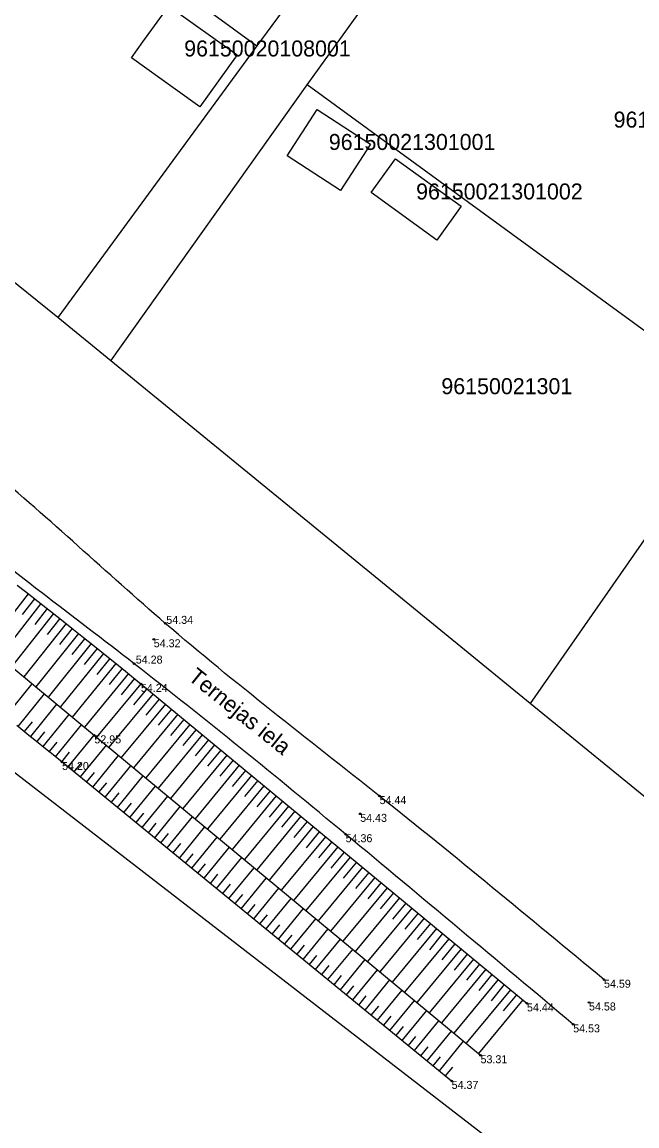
# Model space of a CAD drawing. Extents: x 578395 to 578590, y 418519 to 418816.
# Drawn here: x 578503.6 to 578542.1, y 418577.2 to 418646.2 of the extents above; entities that cross this region are included whole.
import ezdxf

# ---------------------------------------------------------------- set-up
doc = ezdxf.new("R2010")
doc.units = 0
for name, color, linetype in [('BUVE_EKAS_UZMR_####_#', 7, 'Continuous'), ('BUVE_EKAS_UZMR_TKST_#', 7, 'Continuous'), ('BUVE_EKAS_VEKT_####_#', 7, 'Continuous'), ('BUVE_EKAS_VEKT_TKST_#', 7, 'Continuous'), ('CELI_CMAL_####_####_#', 7, 'Continuous'), ('CELI_IELA_####_TKST_#', 7, 'Continuous'), ('RELJ_AATZ_####_TKST_#', 7, 'Continuous'), ('RELJ_ELEM_####_####_#', 7, 'Continuous'), ('RELJ_NOGA_####_####_#', 7, 'Continuous'), ('RELJ_NOGL_####_####_#', 7, 'Continuous'), ('ROBZ_PROJ_####_####_#', 7, 'Continuous'), ('ROBZ_PROJ_####_TKST_#', 7, 'Continuous'), ('ROBZ_UZMR_####_####_#', 7, 'Continuous'), ('ROBZ_UZMR_####_TKST_#', 7, 'Continuous')]:
    doc.layers.add(name, color=color, linetype=linetype)

msp = doc.modelspace()

# ---------------------------------------------------------------- linework, layer by layer
at = {"layer": 'BUVE_EKAS_UZMR_####_#'}
for p, q in [((578511.2, 418644.98), (578512.807, 418647.212)), ((578512.807, 418647.212), (578517.09, 418644.18)), ((578510.48, 418643.99), (578511.2, 418644.98)), ((578513.21, 418642.02), (578510.48, 418643.99)), ((578517.09, 418644.18), (578514.75, 418640.93)), ((578514.75, 418640.93), (578513.21, 418642.02))]:
    msp.add_line(p, q, dxfattribs=at)
at = {"layer": 'BUVE_EKAS_VEKT_####_#'}
for p, q in [((578520.204, 418637.867), (578522.088, 418640.763)), ((578522.088, 418640.763), (578525.431, 418638.589)), ((578525.431, 418638.589), (578523.548, 418635.692)), ((578523.548, 418635.692), (578520.204, 418637.867)), ((578525.461, 418635.561), (578526.984, 418637.669)), ((578526.984, 418637.669), (578531.085, 418634.707)), ((578529.562, 418632.599), (578525.461, 418635.561)), ((578531.085, 418634.707), (578529.562, 418632.599))]:
    msp.add_line(p, q, dxfattribs=at)
at = {"layer": 'CELI_CMAL_####_####_#'}
for points in [[(578540.02, 418586.371), (578525.988, 418597.847), (578512.594, 418608.642), (578501.669, 418618.235), (578486.368, 418629.744), (578473.85, 418639.529), (578461.404, 418649.849), (578445.482, 418664.308), (578434.891, 418671.618), (578433.593, 418673.245), (578433.709, 418674.571), (578434.344, 418682.513), (578433.832, 418698.668), (578431.508, 418715.146), (578429.961, 418730.384), (578428.634, 418741.31), (578426.857, 418755.172), (578424.464, 418771.373), (578422.35, 418787.381), (578420.601, 418802.682)], [(578538.092, 418583.58), (578523.866, 418595.463), (578510.65, 418606.122), (578499.131, 418615.129), (578484.947, 418627.43), (578472.156, 418636.888), (578459.663, 418647.262), (578443.345, 418661.302), (578436.955, 418666.057), (578434.564, 418667.369), (578433.603, 418667.727)]]:
    msp.add_spline(points, degree=3, dxfattribs=at)
at = {"layer": 'RELJ_ELEM_####_####_#'}
for centre in [(578512.594, 418608.642), (578511.874, 418607.649), (578510.65, 418606.122), (578511.07, 418604.859), (578508.16, 418601.644), (578506.143, 418599.979), (578525.988, 418597.847), (578524.779, 418596.738), (578523.866, 418595.463), (578540.02, 418586.371), (578535.205, 418584.891), (578539.082, 418584.949), (578538.092, 418583.58), (578532.302, 418581.652), (578530.493, 418580.048)]:
    msp.add_circle(centre, 0.05, dxfattribs=at)
at = {"layer": 'RELJ_NOGA_####_####_#'}
for p, q in [((578504.028, 418610.491), (578501.459, 418607.198)), ((578504.816, 418609.876), (578502.222, 418606.565)), ((578504.422, 418610.184), (578503.649, 418609.192)), ((578505.603, 418609.259), (578502.986, 418605.931)), ((578505.21, 418609.568), (578504.429, 418608.571)), ((578506.388, 418608.64), (578503.75, 418605.298)), ((578505.996, 418608.949), (578505.207, 418607.95)), ((578506.78, 418608.329), (578505.985, 418607.326)), ((578507.172, 418608.018), (578504.508, 418604.67)), ((578507.563, 418607.706), (578506.759, 418606.702)), ((578507.953, 418607.394), (578505.27, 418604.039)), ((578508.343, 418607.081), (578507.533, 418606.076)), ((578508.733, 418606.767), (578506.028, 418603.41)), ((578509.122, 418606.453), (578508.306, 418605.447)), ((578509.51, 418606.138), (578506.78, 418602.788)), ((578509.897, 418605.822), (578509.077, 418604.816)), ((578510.284, 418605.506), (578507.539, 418602.158)), ((578510.671, 418605.188), (578509.844, 418604.186)), ((578502.627, 418602.822), (578504.267, 418604.87)), ((578503.407, 418602.196), (578505.042, 418604.228)), ((578511.056, 418604.87), (578508.3, 418601.528)), ((578511.827, 418604.233), (578509.065, 418600.895)), ((578511.442, 418604.551), (578510.613, 418603.55)), ((578504.186, 418601.569), (578505.815, 418603.587)), ((578512.597, 418603.595), (578509.835, 418600.257)), ((578512.212, 418603.914), (578511.384, 418602.913)), ((578504.963, 418600.94), (578506.589, 418602.946)), ((578513.368, 418602.958), (578510.605, 418599.619)), ((578512.983, 418603.277), (578512.154, 418602.275)), ((578503.797, 418601.883), (578504.286, 418602.491)), ((578505.739, 418600.309), (578507.366, 418602.302)), ((578514.138, 418602.32), (578511.376, 418598.981)), ((578513.753, 418602.639), (578512.924, 418601.637)), ((578504.575, 418601.255), (578505.064, 418601.858)), ((578506.513, 418599.676), (578508.139, 418601.662)), ((578514.909, 418601.683), (578512.146, 418598.343)), ((578514.524, 418602.002), (578513.695, 418601)), ((578505.351, 418600.625), (578505.839, 418601.224)), ((578507.287, 418599.043), (578508.909, 418601.024)), ((578515.679, 418601.045), (578512.916, 418597.706)), ((578515.294, 418601.364), (578514.465, 418600.362)), ((578506.126, 418599.993), (578506.614, 418600.59)), ((578508.061, 418598.409), (578509.679, 418600.386)), ((578516.45, 418600.408), (578513.686, 418597.068)), ((578516.065, 418600.727), (578515.236, 418599.725)), ((578516.835, 418600.089), (578516.006, 418599.087)), ((578506.9, 418599.359), (578507.387, 418599.954)), ((578508.835, 418597.776), (578510.449, 418599.748)), ((578517.22, 418599.771), (578514.456, 418596.43)), ((578517.606, 418599.452), (578516.776, 418598.45)), ((578507.674, 418598.726), (578508.16, 418599.32)), ((578508.448, 418598.093), (578508.933, 418598.685)), ((578509.608, 418597.142), (578511.219, 418599.111)), ((578517.991, 418599.133), (578515.227, 418595.792)), ((578518.376, 418598.814), (578517.547, 418597.812)), ((578509.222, 418597.459), (578509.705, 418598.05)), ((578510.382, 418596.509), (578511.99, 418598.473)), ((578518.761, 418598.496), (578515.997, 418595.154)), ((578519.147, 418598.177), (578518.317, 418597.174)), ((578509.995, 418596.826), (578510.478, 418597.415)), ((578511.156, 418595.876), (578512.76, 418597.835)), ((578519.532, 418597.858), (578516.767, 418594.516)), ((578519.917, 418597.539), (578519.088, 418596.537)), ((578510.769, 418596.192), (578511.251, 418596.781)), ((578511.93, 418595.242), (578513.53, 418597.197)), ((578520.302, 418597.221), (578517.537, 418593.879)), ((578520.688, 418596.902), (578519.858, 418595.899)), ((578511.543, 418595.559), (578512.024, 418596.146)), ((578512.704, 418594.609), (578514.3, 418596.559)), ((578513.478, 418593.975), (578515.07, 418595.921)), ((578521.073, 418596.583), (578518.307, 418593.241)), ((578521.843, 418595.946), (578519.078, 418592.603)), ((578521.458, 418596.265), (578520.628, 418595.262)), ((578512.317, 418594.926), (578512.796, 418595.511)), ((578514.251, 418593.342), (578515.841, 418595.284)), ((578522.614, 418595.308), (578519.848, 418591.965)), ((578522.228, 418595.627), (578521.399, 418594.624)), ((578513.091, 418594.292), (578513.569, 418594.877)), ((578515.025, 418592.709), (578516.611, 418594.646)), ((578523.384, 418594.671), (578520.618, 418591.327)), ((578522.999, 418594.99), (578522.169, 418593.987)), ((578513.865, 418593.659), (578514.342, 418594.242)), ((578515.799, 418592.075), (578517.381, 418594.008)), ((578524.155, 418594.033), (578521.388, 418590.69)), ((578523.769, 418594.352), (578522.94, 418593.349)), ((578514.638, 418593.025), (578515.115, 418593.607)), ((578516.573, 418591.442), (578518.151, 418593.37)), ((578524.925, 418593.396), (578522.158, 418590.052)), ((578524.54, 418593.715), (578523.71, 418592.712)), ((578515.412, 418592.392), (578515.887, 418592.972)), ((578517.347, 418590.808), (578518.922, 418592.732)), ((578525.696, 418592.759), (578522.929, 418589.414)), ((578525.31, 418593.077), (578524.48, 418592.074)), ((578516.186, 418591.759), (578516.66, 418592.338)), ((578518.121, 418590.175), (578519.692, 418592.095)), ((578526.466, 418592.121), (578523.699, 418588.776)), ((578526.081, 418592.44), (578525.251, 418591.436)), ((578526.851, 418591.802), (578526.021, 418590.799)), ((578516.96, 418591.125), (578517.433, 418591.703)), ((578518.894, 418589.542), (578520.462, 418591.457)), ((578527.237, 418591.484), (578524.469, 418588.138)), ((578527.622, 418591.165), (578526.792, 418590.161)), ((578517.734, 418590.492), (578518.206, 418591.068)), ((578518.508, 418589.858), (578518.978, 418590.434)), ((578519.668, 418588.908), (578521.232, 418590.819)), ((578528.007, 418590.846), (578525.239, 418587.501)), ((578528.392, 418590.527), (578527.562, 418589.524)), ((578519.281, 418589.225), (578519.751, 418589.799)), ((578520.442, 418588.275), (578522.002, 418590.181)), ((578528.778, 418590.209), (578526.009, 418586.863)), ((578529.163, 418589.89), (578528.332, 418588.886)), ((578520.055, 418588.592), (578520.524, 418589.164)), ((578521.216, 418587.641), (578522.773, 418589.543)), ((578529.548, 418589.571), (578526.78, 418586.225)), ((578529.933, 418589.252), (578529.103, 418588.249)), ((578520.829, 418587.958), (578521.297, 418588.529)), ((578521.99, 418587.008), (578523.543, 418588.905)), ((578530.319, 418588.934), (578527.55, 418585.587)), ((578530.704, 418588.615), (578529.873, 418587.611)), ((578521.603, 418587.325), (578522.069, 418587.895)), ((578522.764, 418586.375), (578524.313, 418588.268)), ((578523.537, 418585.741), (578525.083, 418587.63)), ((578531.089, 418588.296), (578528.32, 418584.949)), ((578531.86, 418587.659), (578529.09, 418584.312)), ((578531.474, 418587.978), (578530.644, 418586.973)), ((578522.377, 418586.691), (578522.842, 418587.26)), ((578524.311, 418585.108), (578525.853, 418586.992)), ((578532.63, 418587.021), (578529.86, 418583.674)), ((578532.245, 418587.34), (578531.414, 418586.336)), ((578523.15, 418586.058), (578523.615, 418586.625)), ((578525.085, 418584.475), (578526.624, 418586.354)), ((578533.401, 418586.384), (578530.631, 418583.036)), ((578533.015, 418586.703), (578532.184, 418585.698)), ((578523.924, 418585.425), (578524.388, 418585.991)), ((578525.859, 418583.841), (578527.394, 418585.716)), ((578534.171, 418585.746), (578531.401, 418582.398)), ((578533.786, 418586.065), (578532.955, 418585.061)), ((578524.698, 418584.791), (578525.16, 418585.356)), ((578526.633, 418583.208), (578528.164, 418585.079)), ((578534.941, 418585.109), (578532.171, 418581.76)), ((578534.556, 418585.428), (578533.725, 418584.423)), ((578525.472, 418584.158), (578525.933, 418584.721)), ((578527.407, 418582.574), (578528.934, 418584.441)), ((578526.246, 418583.524), (578526.706, 418584.086)), ((578528.18, 418581.941), (578529.704, 418583.803)), ((578527.02, 418582.891), (578527.478, 418583.452)), ((578527.793, 418582.258), (578528.251, 418582.817)), ((578528.954, 418581.308), (578530.475, 418583.165)), ((578528.567, 418581.624), (578529.024, 418582.182)), ((578529.728, 418580.674), (578531.245, 418582.527)), ((578529.341, 418580.991), (578529.797, 418581.547)), ((578530.115, 418580.357), (578530.569, 418580.913))]:
    msp.add_line(p, q, dxfattribs=at)
for points in [[(578503.328, 418611.036), (578503.854, 418610.628), (578504.641, 418610.013), (578505.428, 418609.397), (578505.82, 418609.088), (578506.517, 418608.538), (578506.865, 418608.262), (578507.386, 418607.848), (578508.166, 418607.224), (578508.944, 418606.598), (578509.332, 418606.283), (578510.106, 418605.652), (578510.492, 418605.336), (578511.07, 418604.859), (578535.205, 418584.891)], [(578503.31, 418602.275), (578504.068, 418601.665), (578504.446, 418601.36), (578505.201, 418600.747), (578505.578, 418600.44), (578506.143, 418599.979), (578530.493, 418580.048)]]:
    msp.add_lwpolyline(points, dxfattribs=at)
at = {"layer": 'RELJ_NOGL_####_####_#'}
msp.add_lwpolyline([(578502.997, 418605.922), (578508.16, 418601.644), (578532.302, 418581.652)], dxfattribs=at)
at = {"layer": 'ROBZ_PROJ_####_####_#'}
for p, q in [((578528.523, 418658.549), (578518.31, 418644.74)), ((578509.193, 418625.052), (578521.455, 418642.291)), ((578456.044, 418635.726), (578533.748, 418575.711)), ((578509.193, 418625.052), (578505.878, 418627.76)), ((578535.407, 418603.639), (578509.193, 418625.052)), ((578548.553, 418622.531), (578535.407, 418603.639)), ((578564.357, 418579.991), (578535.407, 418603.639))]:
    msp.add_line(p, q, dxfattribs=at)
at = {"layer": 'ROBZ_UZMR_####_####_#'}
for p, q in [((578490.35, 418665.18), (578518.31, 418644.74)), ((578521.455, 418642.291), (578531.777, 418656.722)), ((578505.878, 418627.76), (578479.129, 418649.244)), ((578518.31, 418644.74), (578505.878, 418627.76)), ((578548.553, 418622.531), (578521.455, 418642.291))]:
    msp.add_line(p, q, dxfattribs=at)

# ---------------------------------------------------------------- texts
at = {"layer": 'BUVE_EKAS_UZMR_TKST_#'}
msp.add_text('96150020108001', height=1, dxfattribs=at).set_placement((578513.775, 418644.071))
at = {"layer": 'BUVE_EKAS_VEKT_TKST_#'}
for s, p in [('96150021301001', (578522.817, 418638.228)), ('96150021301002', (578528.273, 418635.134))]:
    msp.add_text(s, height=1, dxfattribs=at).set_placement(p)
at = {"layer": 'CELI_IELA_####_TKST_#'}
msp.add_text('Ternejas iela', height=1, rotation=321.22961, dxfattribs=at).set_placement((578513.961, 418605.158))
at = {"layer": 'RELJ_AATZ_####_TKST_#'}
for s, p in [('54.34', (578512.658, 418608.611)), ('54.32', (578511.874, 418607.149)), ('54.28', (578510.75, 418606.128)), ('54.24', (578511.07, 418604.359)), ('52.95', (578508.16, 418601.144)), ('54.20', (578506.143, 418599.479)), ('54.44', (578525.988, 418597.347)), ('54.43', (578524.779, 418596.238)), ('54.36', (578523.866, 418594.963)), ('54.59', (578540.02, 418585.871)), ('54.44', (578535.205, 418584.391)), ('54.58', (578539.082, 418584.449)), ('54.53', (578538.092, 418583.08)), ('53.31', (578532.302, 418581.152)), ('54.37', (578530.493, 418579.548))]:
    msp.add_text(s, height=0.5, dxfattribs=at).set_placement(p)
at = {"layer": 'ROBZ_PROJ_####_TKST_#'}
msp.add_text('96150021301', height=1, dxfattribs=at).set_placement((578529.853, 418622.965))
at = {"layer": 'ROBZ_UZMR_####_TKST_#'}
msp.add_text('96150021302', height=1, dxfattribs=at).set_placement((578540.621, 418639.626))

doc.saveas('drawing.dxf')
